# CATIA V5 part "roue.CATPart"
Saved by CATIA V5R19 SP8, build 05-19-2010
Part number: roue
Bounding box of the stored display mesh (mm): x -12 to -4, y -15.674 to 15.674, z -61.674 to -30.326
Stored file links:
  C:\Users\rcousturie\Desktop\EU_thinkMotion\iao\IAO_MMS_Groupe1\glenerrant\glenerrant\Nouveau dossier\roue.CATPart
  C:\Program Files\Dassault Systemes\B19\intel_a\startup\materials\French\Catalog.CATMaterial
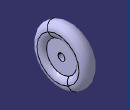
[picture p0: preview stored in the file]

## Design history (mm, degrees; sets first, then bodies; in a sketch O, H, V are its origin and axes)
Line1: stored without definition
Line2: stored without definition
Set1
  Point1: (0, 0, -46)
  Plane1: type Offset, RefPlane yz-plane, Offset -10
  Plane2: type Tangent, Support face of Pad1 from Sketch1.A1, RefPoint Point1
Body1 (main body), material "Aucun"
  Sketch1 on Plane1, origin (-10, 0, 0), H (0, 1, 0), V (0, 0, 1)
    circle A1 centre (0, -46) radius 10
    point P1 (0, -46)
    reference projected point E1 (0, -46) from Point1
    circle A2 centre (0, -46) radius 2
    point P2 (0, -46)
    reference projected point E2 (0, -46) from Point1
    radius A1 = 10
    radius A2 = 2
    coincidence: P1 E1, P2 E2
  Pad1: profile Sketch1, direction (1, 0, 0), length 4
  Sketch2 on Plane2, origin (0, 0, 0), H (1, 0, 0), V (0, 0, 1)
    circle A1 centre (-8, -58) radius 4
    point P1 (-8, -58)
    reference projected line E1 through (0, -46) direction (1, 0) from axis of face of Pad1 from Sketch1.A1
    reference intersected line E2 through (-10, 0) direction (0, 1) from Plane1
    radius A1 = 4
    distance E1 P1 = 12
    distance P1 E2 = 2
  Shaft1: profile Sketch2, axis axis of face of Pad1 from Sketch1.A2, angle 360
